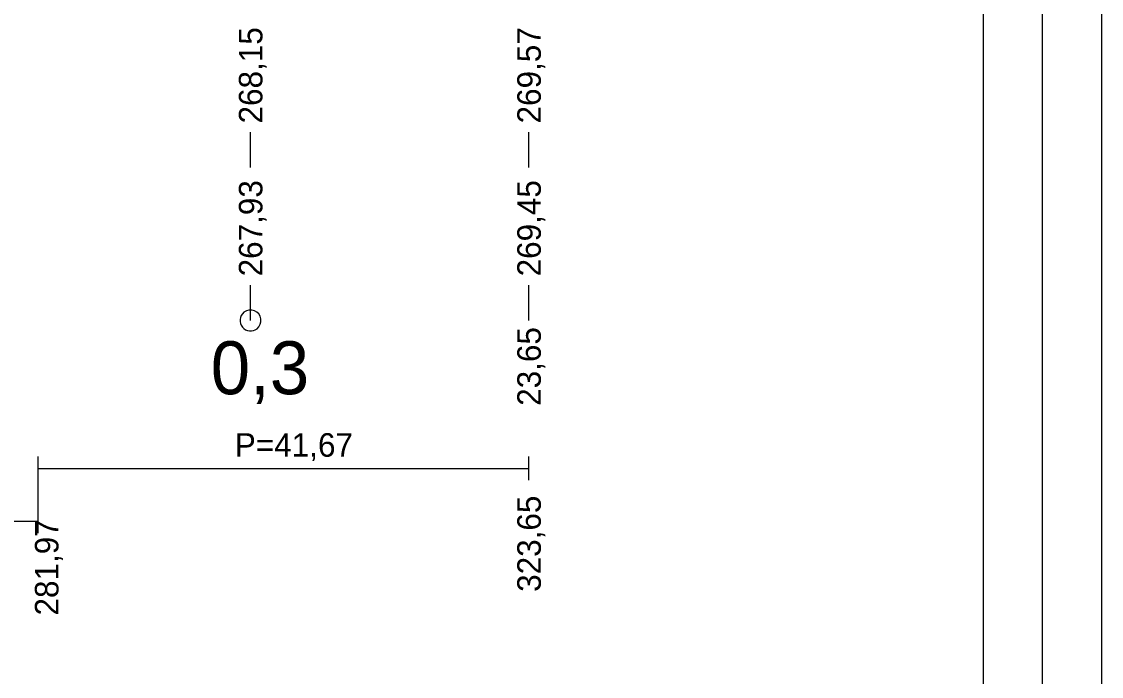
# Model space of a CAD drawing. Extents: x -762531 to -762101, y -1049246 to -1048939.
# Drawn here: x -762192.8 to -762101.1, y -1049151.6 to -1049095.9 of the extents above; entities that cross this region are included whole.
import ezdxf

# ---------------------------------------------------------------- set-up
doc = ezdxf.new("R2010")
doc.units = 0
for name, color, linetype in [('C3D-ZOBPROF-PROUZEK-NAVRH', 7, 'Continuous'), ('C3D-ZOBPROF-PROUZEK-POPIS', 7, 'Continuous'), ('C3D-ZOBPROF-PROUZEK-TEREN', 7, 'Continuous'), ('Default', 7, 'Continuous'), ('U_formát', 7, 'Continuous'), ('U_rozvržení_rámeček', 7, 'Continuous')]:
    doc.layers.add(name, color=color, linetype=linetype)

# ---------------------------------------------------------------- blocks, each defined once
blk = doc.blocks.new('U1096')
at = {"layer": 'Default'}
blk.add_lwpolyline([(0, -297), (0, 0), (-420, 0), (-420, -297)], close=True, dxfattribs=at)
at = {"layer": 'U_formát'}
for points in [[(-425, 5), (5, 5), (5, -302), (-425, -302)], [(-5, -292), (-5, -5), (-415, -5), (-415, -292)]]:
    blk.add_lwpolyline(points, close=True, dxfattribs=at)

msp = doc.modelspace()

# ---------------------------------------------------------------- linework, layer by layer
at = {"layer": 'C3D-ZOBPROF-PROUZEK-NAVRH'}
for p, q in [((-762191.406, -1049134.927), (-762191.406, -1049132.927)), ((-762149.731, -1049134.927), (-762149.731, -1049132.927)), ((-762191.406, -1049138.427), (-762191.406, -1049133.927)), ((-762191.406, -1049133.927), (-762149.731, -1049133.927)), ((-762191.406, -1049139.427), (-762191.406, -1049137.427)), ((-762229.582, -1049138.427), (-762191.406, -1049138.427))]:
    msp.add_line(p, q, dxfattribs=at)
at = {"layer": 'C3D-ZOBPROF-PROUZEK-POPIS'}
for start, end in [(128.65981, 308.65981), (308.65981, 128.65981)]:
    msp.add_arc((-762173.376, -1049121.358), 0.89, start, end, dxfattribs=at)
at = {"layer": 'C3D-ZOBPROF-PROUZEK-TEREN'}
for p, q in [((-762173.376, -1049108.358), (-762173.376, -1049105.358)), ((-762149.731, -1049108.358), (-762149.731, -1049105.358)), ((-762173.376, -1049121.358), (-762173.376, -1049118.358)), ((-762149.731, -1049121.358), (-762149.731, -1049118.358))]:
    msp.add_line(p, q, dxfattribs=at)

# ---------------------------------------------------------------- block references
at = {"layer": 'U_rozvržení_rámeček'}
msp.add_blockref('U1096', (-762106.113, -1048944.389), dxfattribs=at)

# ---------------------------------------------------------------- texts
at = {"layer": 'C3D-ZOBPROF-PROUZEK-NAVRH'}
msp.add_text('P=41,67', height=2, dxfattribs=at).set_placement((-762174.711, -1049132.935))
for s, p in [('323,65', (-762148.723, -1049144.422)), ('281,97', (-762189.689, -1049146.434))]:
    msp.add_text(s, height=2, rotation=90, dxfattribs=at).set_placement(p)
at = {"layer": 'C3D-ZOBPROF-PROUZEK-POPIS'}
msp.add_text('0,3', height=4.5, dxfattribs=at).set_placement((-762176.757, -1049127.625))
at = {"layer": 'C3D-ZOBPROF-PROUZEK-TEREN'}
for s, p in [('268,15', (-762172.368, -1049104.608)), ('269,57', (-762148.723, -1049104.608)), ('267,93', (-762172.368, -1049117.608)), ('269,45', (-762148.723, -1049117.608)), ('23,65', (-762148.723, -1049128.61))]:
    msp.add_text(s, height=2, rotation=90, dxfattribs=at).set_placement(p)

doc.saveas('drawing.dxf')
